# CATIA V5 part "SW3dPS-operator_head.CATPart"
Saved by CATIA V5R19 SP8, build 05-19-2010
Part number: SW3dPS-operator_head
Revision: ANY
Definition: SW3dPS-operator_head
Source: Unknown
Bounding box of the stored display mesh (mm): x -210.642 to 107.95, y -133.307 to 107.95, z -81.726 to 81.726
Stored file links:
  G:\EU_thinkMotion\CFAO_2010\MMS_groupe1\MMS_groupe1\OK\rragonneau\rragonneau\SW3dPS-operator_head.CATPart
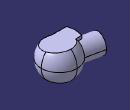
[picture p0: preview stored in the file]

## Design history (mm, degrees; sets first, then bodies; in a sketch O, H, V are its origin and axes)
Body1 "NONE" (main body)
  Solid1 "Manifold Solid #12203": solid without history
